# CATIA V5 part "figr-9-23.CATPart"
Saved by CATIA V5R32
Part number: Part2
Bounding box of the stored display mesh (mm): x -72 to 72, y -80 to 90, z -20 to 41.296
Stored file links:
  D:\PROJECTS\Project 2022\CATIA V5 6R 2022\Resources\Part Files\c09_catia_v5_6r2022_prt\c09_catia_v5_6r2022_prt\figr-9-23.CATPart
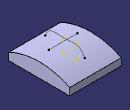
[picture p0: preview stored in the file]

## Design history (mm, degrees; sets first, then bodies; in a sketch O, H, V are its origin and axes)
Body1 (main body)
  Sketch1 on yz-plane, origin (0, 0, 0), H (0, 1, 0), V (0, 0, 1)
    arc A1 centre (5, -170) radius 190.0658 from (-80, 0) to (90, 0) cw
    point P2 (-80, 0)
    point P3 (0, 20)
    line L1 (-80, 0) -> (-80, -20)
    line L2 (-80, -20) -> (90, -20)
    line L3 (90, -20) -> (90, 0)
    coincidence: P2 H, A1 P3, P3 V
    vertical: L1 V, L3 V
    horizontal: L2 H
  Pad1: profile Sketch1, direction (1, 0, 0), length 72, mirrored extent
  Sketch2 on zx-plane, origin (0, 0, 0), H (-1, 0, 0), V (0, 0, 1)
    line L1 (-40, 30) -> (40, 30)
    horizontal: L1 H
  Sketch3 on yz-plane, origin (0, 0, 0), H (0, 1, 0), V (0, 0, 1)
    spline S1 through (60, 20) (40, 40) (10, 40) (-10, 40) (-30, 40) (-50, 20)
